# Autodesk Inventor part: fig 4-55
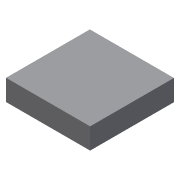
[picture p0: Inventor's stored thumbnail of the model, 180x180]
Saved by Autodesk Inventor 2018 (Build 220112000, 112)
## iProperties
Created: 2010-02
Part Number: fig 4-55
Document SubType Name: Modeling
Designer: CADSoft
Density: 1 g/cm^3
Material: Generic
Appearance: Default
Author: CADSoft
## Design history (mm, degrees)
sketch "Sketch1"
  geometry: L1 (-20.026, 19.961)-(0, 19.961); L2 (0, 19.961)-(0, 0); L3 (0, 0)-(-20.026, 0); L4 (-20.026, 0)-(-20.026, 19.961)
  constraints: 8 end point
extrude "Extrusion1" new body sketch "Sketch1" distance "d0" = 5; taper "d1" = 0 deg
body "Solid1"
